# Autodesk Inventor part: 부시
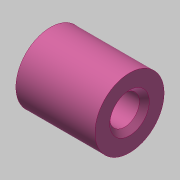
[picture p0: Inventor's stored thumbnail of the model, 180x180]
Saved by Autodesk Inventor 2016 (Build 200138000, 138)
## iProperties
Created: 2019-02
Part Number: 부시
Material: 스테인리스강
Document SubType Name: Modeling
Designer: mduedu
Density: 1 g/cm^3
Appearance: 분홍색
Author: mduedu
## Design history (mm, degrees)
sketch "스케치1"
  geometry: C1 r 3 at (0, 0); C2 r 7 at (0, 0); 1 further point
  constraints: 2 centre point, 2 coincident
  dimensions: "d0" = 6 diameter of C1; "d1" = 14 diameter of C2
extrude "돌출1" new body sketch "스케치1" stored distance "d2" = 16; taper "d3" = 0 deg
chamfer "모따기1" distance "d4" = 1; stored, may be unused: second distance "d5" = 2, angle "d6" = 45 deg
node "솔리드1"
